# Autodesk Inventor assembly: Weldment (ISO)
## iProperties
Length Units: 11269
Angle Units: 11283
Time Units: 11279
Mass Units: 11290
Length Display Precision: 3
Angle Display Precision: 2
Part Number: Weldment (ISO)
Document SubType Name: Weldment
Created: 2002-06
Designer: smithga
Created: 2002-08
Weld Material: Aluminium soudé - 6061
Control State: 0
Master: False
Shininess: 64.0
Angle Units: 11279
Time Units: 11290
Mass Units: 11283
Compacted: True
Density: 0.0
Volumn: 0.0
Area: 0.0
PropertySet Name: Model Information
